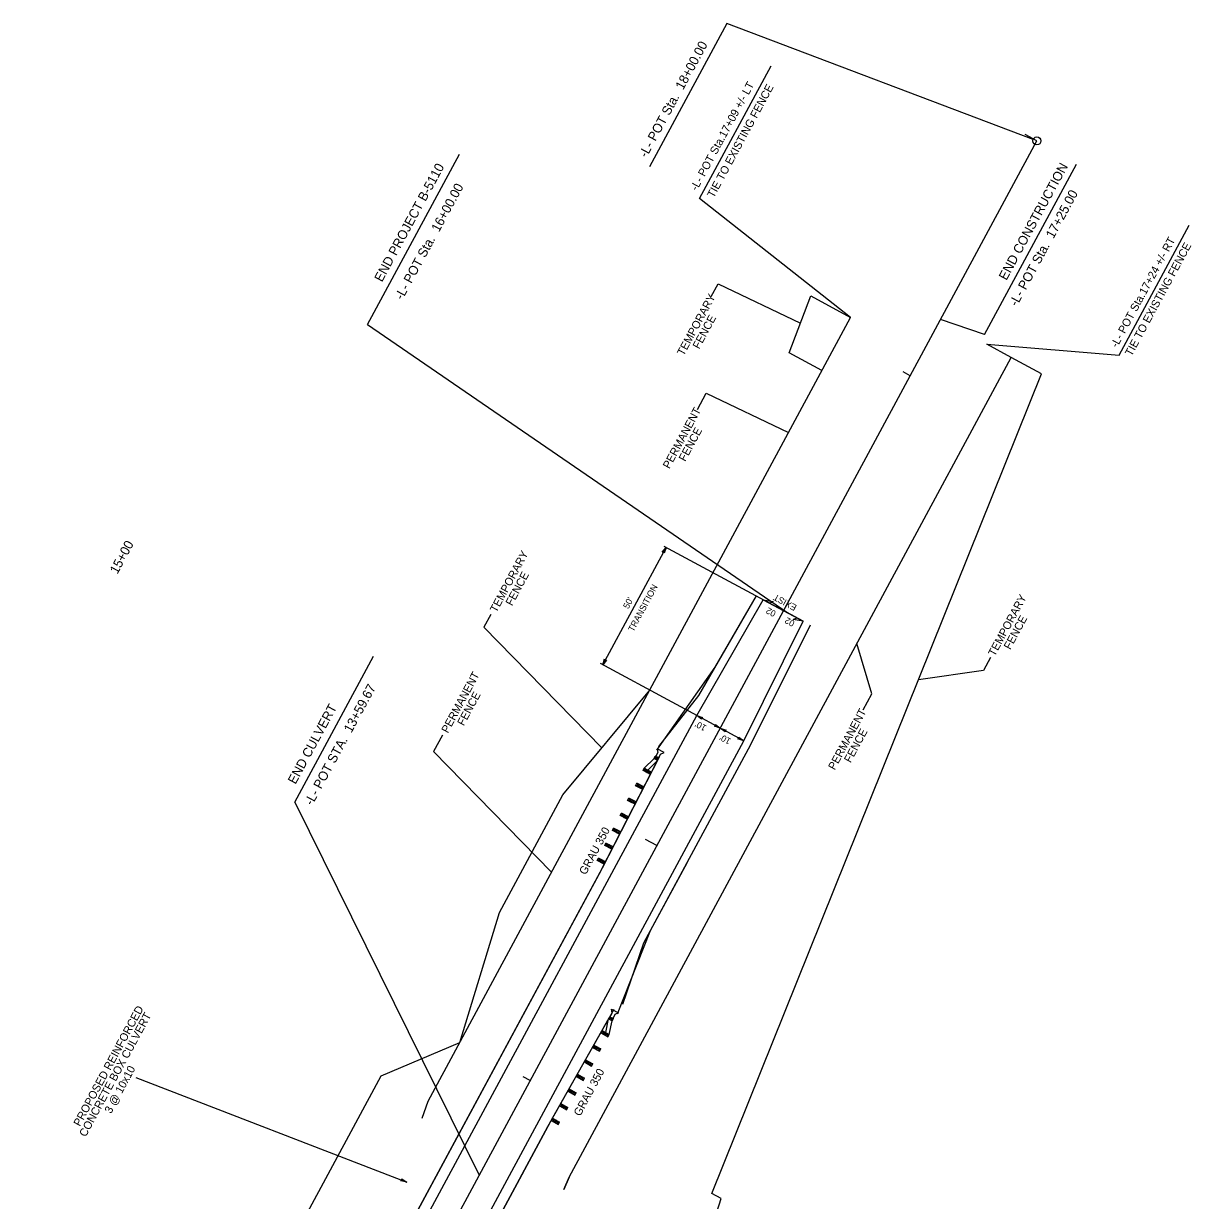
# Model space of a CAD drawing. Extents: x 1376855 to 1377489, y 762573 to 763464.
# Drawn here: x 1377051.8 to 1377489.3, y 763022.8 to 763463.8 of the extents above; entities that cross this region are included whole.
import ezdxf

# ---------------------------------------------------------------- set-up
doc = ezdxf.new("R2010")
doc.units = 0
for name, color, linetype in [('Prop Dimension', 7, 'Continuous'), ('Prop Dimension Text', 7, 'Continuous'), ('Prop EOT', 7, 'Continuous'), ('Prop Fence Barbed Wire', 7, 'Continuous'), ('Prop Guardrail Anchor Unit CELL', 7, 'Continuous'), ('Prop Horizontal Alignment', 7, 'Continuous'), ('Prop Horizontal Alignment Station Label', 7, 'Continuous'), ('Prop Horizontal Alignment Tick Label', 7, 'Continuous'), ('Prop Horizontal Alignment Tick Large', 7, 'Continuous'), ('Prop Horizontal Alignment Tick Small', 7, 'Continuous'), ('Prop Superelevation  Arrow CELL', 7, 'Continuous'), ('Prop Terminator CELL', 7, 'Continuous'), ('Scratch_Level_1', 7, 'Continuous'), ('Scratch_Level_2', 7, 'Continuous'), ('Scratch_Level_6', 7, 'Continuous')]:
    doc.layers.add(name, color=color, linetype=linetype)

msp = doc.modelspace()

# ---------------------------------------------------------------- linework, layer by layer
at = {"layer": 'Prop Dimension'}
for p, q in [((1377305.05, 763398.25), (1377331.81, 763447.9)), ((1377180.66, 763350.97), (1377215.07, 763414.8)), ((1377411.81, 763347.28), (1377446.22, 763411.11)), ((1377361.64, 763353.63), (1377305.05, 763398.25)), ((1377462.19, 763339.49), (1377488.46, 763388.21)), ((1377309.4, 763361.45), (1377311.97, 763366.23)), ((1377311.97, 763366.23), (1377342.81, 763351.49)), ((1377411.81, 763347.28), (1377395.34, 763352.92)), ((1377180.66, 763350.97), (1377338.08, 763242.92)), ((1377412.63, 763343.6), (1377462.19, 763339.49)), ((1377304.28, 763319.15), (1377307.56, 763325.23)), ((1377307.56, 763325.23), (1377338.39, 763310.5)), ((1377268.76, 763223.49), (1377292.49, 763267.5)), ((1377291.61, 763267.97), (1377343.89, 763239.78)), ((1377226.81, 763242.34), (1377224.23, 763237.56)), ((1377224.23, 763237.56), (1377268.43, 763192.34)), ((1377369.62, 763212.65), (1377363.94, 763231.45)), ((1377321.57, 763195.01), (1377267.88, 763223.96)), ((1377413.99, 763226.18), (1377411.41, 763221.4)), ((1377411.41, 763221.4), (1377387.05, 763217.81)), ((1377366.34, 763206.57), (1377369.62, 763212.65)), ((1377208.67, 763197.07), (1377205.39, 763190.99)), ((1377205.39, 763190.99), (1377249.58, 763145.77)), ((1377093.88, 763068.86), (1377195.41, 763029.67))]:
    msp.add_line(p, q, dxfattribs=at)
at = {"layer": 'Prop EOT'}
for p, q in [((1377303.97, 763204.51), (1377328.91, 763247.86)), ((1377343.89, 763239.78), (1377328.91, 763247.86)), ((1377321.57, 763195.01), (1377343.89, 763239.78)), ((1377114.15, 762852.41), (1377303.97, 763204.51)), ((1377131.76, 762842.92), (1377321.57, 763195.01))]:
    msp.add_line(p, q, dxfattribs=at)
at = {"layer": 'Prop Fence Barbed Wire'}
for p, q in [((1377338.58, 763340.35), (1377346.68, 763361.69)), ((1377346.68, 763361.69), (1377361.64, 763353.63)), ((1377203.32, 763059.96), (1377361.64, 763353.63)), ((1377421.75, 763338.68), (1377412.63, 763343.6)), ((1377256.13, 763031.48), (1377421.75, 763338.68)), ((1377350.9, 763333.71), (1377338.58, 763340.35)), ((1377433.19, 763332.51), (1377421.75, 763338.68)), ((1377309.64, 763025.36), (1377433.19, 763332.51)), ((1377253.84, 763174.73), (1377286.37, 763214)), ((1377230.11, 763130.72), (1377253.84, 763174.73)), ((1377268.17, 763146.53), (1377181.82, 762986.36)), ((1377215.18, 763081.96), (1377230.11, 763130.72)), ((1377185.72, 763069.45), (1377215.18, 763081.96)), ((1377157.24, 763016.63), (1377185.72, 763069.45)), ((1377201.17, 763053.56), (1377203.32, 763059.96)), ((1377161.86, 762890.33), (1377248.21, 763050.51)), ((1377256.13, 763031.48), (1377254.23, 763026.85)), ((1377254.23, 763026.85), (1377256.13, 763031.48)), ((1377313.16, 763023.46), (1377309.64, 763025.36)), ((1377309.7, 763012.83), (1377313.16, 763023.46))]:
    msp.add_line(p, q, dxfattribs=at)
at = {"layer": 'Prop Guardrail Anchor Unit CELL'}
for p, q in [((1377287.97, 763188.36), (1377288.43, 763189.25)), ((1377287.97, 763188.36), (1377288.2, 763188.81)), ((1377289.37, 763190.57), (1377288.4, 763188.76)), ((1377288.4, 763188.76), (1377288.94, 763188.47)), ((1377289.76, 763188.57), (1377288.43, 763189.25)), ((1377288.43, 763189.25), (1377289.3, 763187.68)), ((1377291.76, 763190.62), (1377289.17, 763192.01)), ((1377289.17, 763192.01), (1377289.37, 763190.57)), ((1377289.48, 763188.19), (1377290.45, 763189.99)), ((1377290.45, 763189.99), (1377291.76, 763190.62)), ((1377268.17, 763146.53), (1377289.53, 763188.12)), ((1377283.88, 763183.83), (1377284.34, 763184.72)), ((1377284.34, 763184.72), (1377287.97, 763188.36)), ((1377287.06, 763183.32), (1377284.34, 763184.72)), ((1377284.34, 763184.72), (1377285.24, 763183.13)), ((1377285.7, 763184.02), (1377289.3, 763187.68)), ((1377289.76, 763188.57), (1377287.97, 763188.36)), ((1377289.3, 763187.68), (1377287.97, 763188.36)), ((1377288.94, 763188.47), (1377289.48, 763188.19)), ((1377285.7, 763184.02), (1377283.88, 763183.83)), ((1377286.61, 763182.43), (1377283.88, 763183.83)), ((1377285.24, 763183.13), (1377285.7, 763184.02)), ((1377285.24, 763183.13), (1377287.06, 763183.32)), ((1377286.61, 763182.43), (1377285.7, 763184.02)), ((1377281.06, 763178.19), (1377281.52, 763179.08)), ((1377282.85, 763178.4), (1377281.06, 763178.19)), ((1377283.73, 763176.82), (1377281.06, 763178.19)), ((1377284.19, 763177.71), (1377281.52, 763179.08)), ((1377281.52, 763179.08), (1377282.39, 763177.51)), ((1377282.39, 763177.51), (1377282.85, 763178.4)), ((1377282.39, 763177.51), (1377284.19, 763177.71)), ((1377283.73, 763176.82), (1377282.85, 763178.4)), ((1377278.06, 763172.65), (1377278.52, 763173.54)), ((1377279.91, 763172.82), (1377278.06, 763172.65)), ((1377280.85, 763171.22), (1377278.06, 763172.65)), ((1377281.31, 763172.11), (1377278.52, 763173.54)), ((1377278.52, 763173.54), (1377279.45, 763171.93)), ((1377279.45, 763171.93), (1377279.91, 763172.82)), ((1377279.45, 763171.93), (1377281.31, 763172.11)), ((1377280.85, 763171.22), (1377279.91, 763172.82)), ((1377275.27, 763167), (1377275.73, 763167.89)), ((1377277.08, 763167.2), (1377275.27, 763167)), ((1377277.97, 763165.61), (1377275.27, 763167)), ((1377278.43, 763166.5), (1377275.73, 763167.89)), ((1377275.73, 763167.89), (1377276.62, 763166.31)), ((1377276.62, 763166.31), (1377277.08, 763167.2)), ((1377277.97, 763165.61), (1377277.08, 763167.2)), ((1377272.38, 763161.4), (1377272.84, 763162.29)), ((1377275.55, 763160.9), (1377272.84, 763162.29)), ((1377272.84, 763162.29), (1377273.74, 763160.7)), ((1377276.62, 763166.31), (1377278.43, 763166.5)), ((1377277.97, 763165.61), (1377278.43, 763166.5)), ((1377274.19, 763161.59), (1377272.38, 763161.4)), ((1377275.09, 763160.01), (1377272.38, 763161.4)), ((1377273.74, 763160.7), (1377274.19, 763161.59)), ((1377273.74, 763160.7), (1377275.55, 763160.9)), ((1377275.09, 763160.01), (1377274.19, 763161.59)), ((1377269.5, 763155.8), (1377269.95, 763156.69)), ((1377271.31, 763155.99), (1377269.5, 763155.8)), ((1377272.21, 763154.4), (1377269.5, 763155.8)), ((1377272.67, 763155.29), (1377269.95, 763156.69)), ((1377269.95, 763156.69), (1377270.86, 763155.1)), ((1377270.86, 763155.1), (1377271.31, 763155.99)), ((1377270.86, 763155.1), (1377272.67, 763155.29)), ((1377272.21, 763154.4), (1377271.31, 763155.99)), ((1377266.67, 763150.17), (1377267.12, 763151.06)), ((1377268.46, 763150.37), (1377266.67, 763150.17)), ((1377269.33, 763148.8), (1377266.67, 763150.17)), ((1377269.79, 763149.69), (1377267.12, 763151.06)), ((1377267.12, 763151.06), (1377268, 763149.48)), ((1377268, 763149.48), (1377268.46, 763150.37)), ((1377268, 763149.48), (1377269.79, 763149.69)), ((1377269.79, 763149.69), (1377268.46, 763150.37)), ((1377268.46, 763150.37), (1377269.33, 763148.8)), ((1377269.33, 763148.8), (1377269.79, 763149.69)), ((1377271.3, 763091.2), (1377272.27, 763093)), ((1377271.46, 763091.64), (1377272.77, 763090.9)), ((1377271.46, 763091.64), (1377272.28, 763090.03)), ((1377272.27, 763093), (1377272.08, 763094.44)), ((1377272.08, 763094.44), (1377274.66, 763093.04)), ((1377273.35, 763092.41), (1377272.37, 763090.61)), ((1377274.66, 763093.04), (1377273.35, 763092.41)), ((1377248.21, 763050.51), (1377271.22, 763091.21)), ((1377269.89, 763085.75), (1377270.97, 763090.77)), ((1377272.77, 763090.9), (1377270.97, 763090.77)), ((1377270.97, 763090.77), (1377272.28, 763090.03)), ((1377271.23, 763085), (1377272.28, 763090.03)), ((1377271.83, 763090.9), (1377271.3, 763091.2)), ((1377272.37, 763090.61), (1377271.83, 763090.9)), ((1377272.28, 763090.03), (1377272.77, 763090.9)), ((1377272.28, 763090.03), (1377272.52, 763090.47)), ((1377268.07, 763085.63), (1377269.89, 763085.75)), ((1377268.07, 763085.63), (1377270.73, 763084.13)), ((1377268.56, 763086.5), (1377271.23, 763085)), ((1377269.4, 763084.88), (1377268.56, 763086.5)), ((1377269.4, 763084.88), (1377269.89, 763085.75)), ((1377271.23, 763085), (1377269.4, 763084.88)), ((1377269.89, 763085.75), (1377270.73, 763084.13)), ((1377270.73, 763084.13), (1377271.23, 763085)), ((1377264.97, 763080.15), (1377266.76, 763080.28)), ((1377264.97, 763080.15), (1377267.58, 763078.67)), ((1377265.46, 763081.02), (1377268.07, 763079.54)), ((1377266.27, 763079.41), (1377265.46, 763081.02)), ((1377266.27, 763079.41), (1377266.76, 763080.28)), ((1377268.07, 763079.54), (1377266.27, 763079.41)), ((1377266.76, 763080.28), (1377267.58, 763078.67)), ((1377267.58, 763078.67), (1377268.07, 763079.54)), ((1377261.87, 763074.66), (1377263.72, 763074.76)), ((1377261.87, 763074.66), (1377264.6, 763073.12)), ((1377262.36, 763075.53), (1377265.09, 763073.99)), ((1377263.23, 763073.89), (1377262.36, 763075.53)), ((1377263.23, 763073.89), (1377263.72, 763074.76)), ((1377265.09, 763073.99), (1377263.23, 763073.89)), ((1377263.72, 763074.76), (1377264.6, 763073.12)), ((1377264.6, 763073.12), (1377265.09, 763073.99)), ((1377258.76, 763069.18), (1377259.26, 763070.05)), ((1377259.26, 763070.05), (1377261.9, 763068.55)), ((1377260.09, 763068.43), (1377259.26, 763070.05)), ((1377258.76, 763069.18), (1377260.58, 763069.3)), ((1377258.76, 763069.18), (1377261.41, 763067.68)), ((1377260.09, 763068.43), (1377260.58, 763069.3)), ((1377261.9, 763068.55), (1377260.09, 763068.43)), ((1377260.58, 763069.3), (1377261.41, 763067.68)), ((1377261.41, 763067.68), (1377261.9, 763068.55)), ((1377255.66, 763063.69), (1377257.48, 763063.81)), ((1377255.66, 763063.69), (1377258.32, 763062.19)), ((1377256.16, 763064.56), (1377258.81, 763063.06)), ((1377256.99, 763062.94), (1377256.16, 763064.56)), ((1377256.99, 763062.94), (1377257.48, 763063.81)), ((1377258.81, 763063.06), (1377256.99, 763062.94)), ((1377257.48, 763063.81), (1377258.32, 763062.19)), ((1377258.32, 763062.19), (1377258.81, 763063.06)), ((1377252.56, 763058.2), (1377254.38, 763058.32)), ((1377252.56, 763058.2), (1377255.22, 763056.7)), ((1377253.06, 763059.07), (1377255.71, 763057.57)), ((1377253.89, 763057.45), (1377253.06, 763059.07)), ((1377253.89, 763057.45), (1377254.38, 763058.32)), ((1377255.71, 763057.57), (1377253.89, 763057.45)), ((1377254.38, 763058.32), (1377255.22, 763056.7)), ((1377255.22, 763056.7), (1377255.71, 763057.57)), ((1377249.46, 763052.72), (1377249.96, 763053.59)), ((1377251.26, 763052.85), (1377249.46, 763052.72)), ((1377249.46, 763052.72), (1377252.07, 763051.24)), ((1377249.96, 763053.59), (1377252.57, 763052.11)), ((1377249.96, 763053.59), (1377251.26, 763052.85)), ((1377250.77, 763051.98), (1377249.96, 763053.59)), ((1377250.77, 763051.98), (1377251.26, 763052.85)), ((1377252.57, 763052.11), (1377250.77, 763051.98)), ((1377251.26, 763052.85), (1377252.07, 763051.24)), ((1377252.07, 763051.24), (1377252.57, 763052.11))]:
    msp.add_line(p, q, dxfattribs=at)
at = {"layer": 'Prop Horizontal Alignment'}
msp.add_line((1377051.77, 762715.63), (1377431.41, 763419.82), dxfattribs=at)
at = {"layer": 'Prop Horizontal Alignment Station Label'}
for p, q in [((1377315.21, 763463.78), (1377286.27, 763410.1)), ((1377430.01, 763420.35), (1377315.21, 763463.78)), ((1377153.35, 763172.03), (1377182.84, 763226.74)), ((1377153.35, 763172.03), (1377222.45, 763032.23))]:
    msp.add_line(p, q, dxfattribs=at)
msp.add_circle((1377431.41, 763419.82), 1.5, dxfattribs=at)
at = {"layer": 'Prop Horizontal Alignment Tick Large'}
msp.add_line((1377289.05, 763155.75), (1377284.82, 763158.03), dxfattribs=at)
at = {"layer": 'Prop Horizontal Alignment Tick Small'}
for p, q in [((1377431.41, 763419.82), (1377427.01, 763422.19)), ((1377383.95, 763331.79), (1377381.31, 763333.22)), ((1377336.81, 763243.61), (1377332.41, 763245.98)), ((1377336.5, 763243.77), (1377333.86, 763245.19)), ((1377241.59, 763067.73), (1377238.95, 763069.15))]:
    msp.add_line(p, q, dxfattribs=at)
at = {"layer": 'Prop Superelevation  Arrow CELL'}
for p, q in [((1377328.91, 763247.86), (1377343.89, 763239.78)), ((1377328.91, 763247.86), (1377335.25, 763244.45)), ((1377343.89, 763239.78), (1377337.56, 763243.2))]:
    msp.add_line(p, q, dxfattribs=at)
for points in [[(1377328.91, 763247.86), (1377332.65, 763247.21), (1377331.35, 763246.55)], [(1377343.89, 763239.78), (1377340.16, 763240.44), (1377341.45, 763241.1)]]:
    msp.add_lwpolyline(points, close=True, dxfattribs=at)
at = {"layer": 'Prop Terminator CELL'}
for points in [[(1377291.08, 763265.7), (1377292.49, 763267.5), (1377291.77, 763265.32), (1377291.55, 763265.76)], [(1377270.17, 763225.28), (1377268.76, 763223.49), (1377269.48, 763225.67), (1377269.7, 763225.23)], [(1377305.77, 763203.1), (1377303.97, 763204.51), (1377306.15, 763203.78), (1377305.71, 763203.57)], [(1377310.98, 763201.17), (1377312.77, 763199.76), (1377310.59, 763200.48), (1377311.03, 763200.7)], [(1377314.57, 763198.35), (1377312.77, 763199.76), (1377314.95, 763199.04), (1377314.51, 763198.82)], [(1377319.78, 763196.42), (1377321.57, 763195.01), (1377319.39, 763195.74), (1377319.84, 763195.95)], [(1377193.45, 763030.84), (1377195.41, 763029.67), (1377193.16, 763030.11), (1377193.57, 763030.38)]]:
    msp.add_lwpolyline(points, close=True, dxfattribs=at)
at = {"layer": 'Scratch_Level_1'}
for p, q in [((1377268.65, 763147.43), (1377290.01, 763189.02)), ((1377185.63, 762993.43), (1377268.65, 763147.43)), ((1377272.93, 763094.38), (1377249.93, 763053.68)), ((1377249.93, 763053.68), (1377167.07, 762900))]:
    msp.add_line(p, q, dxfattribs=at)
at = {"layer": 'Scratch_Level_2'}
for p, q in [((1377304.82, 763212), (1377326.31, 763249.36)), ((1377324.26, 763193.68), (1377346.58, 763238.45)), ((1377289.74, 763192.86), (1377304.82, 763212)), ((1377284.16, 763119.29), (1377324.22, 763193.59)), ((1377276.29, 763096.27), (1377284.16, 763119.29))]:
    msp.add_line(p, q, dxfattribs=at)
at = {"layer": 'Scratch_Level_6'}
for p, q in [((1377310.92, 763222.61), (1377326.31, 763249.36)), ((1377289.03, 763191.54), (1377310.92, 763222.61)), ((1377286.65, 763123.91), (1377300.49, 763149.58)), ((1377274.35, 763092.67), (1377286.65, 763123.91))]:
    msp.add_line(p, q, dxfattribs=at)

# ---------------------------------------------------------------- texts
at = {"layer": 'Prop Dimension Text'}
for s, height, rotation, p in [('-L- POT Sta.17+09 +/- LT', 3, 61.6702, (1377304.04, 763400.9)), ('TIE TO EXISTING FENCE', 3, 61.6702, (1377310.35, 763398.21)), ('END PROJECT B-5110', 3.5, 61.6702, (1377186.06, 763366.68)), ('END CONSTRUCTION', 3.5, 61.6702, (1377420, 763367.3)), ('-L- POT Sta.  16+00.00', 3.5, 61.6702, (1377193.7, 763359.96)), ('-L- POT Sta.  17+25.00', 3.5, 61.6702, (1377423.9, 763357.52)), ('-L- POT Sta.17+24 +/- RT', 3, 61.6702, (1377461.46, 763342.07)), ('TIE TO EXISTING FENCE', 3, 61.6702, (1377466.87, 763338.88)), ('TEMPORARY', 3, 61.6702, (1377299.07, 763339.05)), ('FENCE', 3, 61.6702, (1377304.89, 763341.57)), ('PERMANENT', 3, 61.6702, (1377293.73, 763296.71)), ('FENCE', 3, 61.6702, (1377299.67, 763299.43)), ('TEMPORARY', 3, 61.6702, (1377228.96, 763242.82)), ('FENCE', 3, 61.6702, (1377234.79, 763245.34)), ('TRANSITION', 2.4, 61.6702, (1377280.24, 763235.67)), ("50'", 2.4, 61.6702, (1377278.35, 763244.25)), ('EXIST', 2.4, 151.6702, (1377341.7, 763245.68)), ('TEMPORARY', 3, 61.6702, (1377415.61, 763226.42)), ('FENCE', 3, 61.6702, (1377421.44, 763228.94)), ('PERMANENT', 3, 61.6702, (1377210.76, 763197.65)), ('FENCE', 3, 61.6702, (1377216.7, 763200.38)), ('PERMANENT', 3, 61.6702, (1377355.67, 763183.83)), ("10'", 2.4, 151.6702, (1377307.86, 763200.58)), ('FENCE', 3, 61.6702, (1377361.61, 763186.55)), ("10'", 2.4, 151.6702, (1377317.06, 763195.62)), ('PROPOSED REINFORCED ', 3.006, 61.6702, (1377072.92, 763050.28)), ('CONCRETE BOX CULVERT', 3.006, 61.6702, (1377075.07, 763046.35)), ('3 @ 10x10', 3, 61.6702, (1377084.55, 763055.09))]:
    msp.add_text(s, height=height, rotation=rotation, dxfattribs=at).set_placement(p)
at = {"layer": 'Prop Guardrail Anchor Unit CELL'}
for p in [(1377262.37, 763144.55), (1377260.31, 763054.09)]:
    msp.add_text('GRAU 350', height=3, rotation=61.6702, dxfattribs=at).set_placement(p)
at = {"layer": 'Prop Horizontal Alignment Station Label'}
for s, p in [('-L- POT Sta.  18+00.00', (1377285.16, 763413.25)), ('-L- POT STA.  13+59.67', (1377159.91, 763170.5)), ('END CULVERT', (1377153.65, 763178.49))]:
    msp.add_text(s, height=3.5, rotation=61.6702, dxfattribs=at).set_placement(p)
at = {"layer": 'Prop Horizontal Alignment Tick Label'}
msp.add_text('15+00', height=3.5, rotation=61.6702, dxfattribs=at).set_placement((1377086.94, 763257.25))
at = {"layer": 'Prop Superelevation  Arrow CELL'}
for p in [(1377333.9, 763243.41), (1377340.93, 763239.73)]:
    msp.add_text('02', height=2.4, rotation=151.6702, dxfattribs=at).set_placement(p)

doc.saveas('drawing.dxf')
